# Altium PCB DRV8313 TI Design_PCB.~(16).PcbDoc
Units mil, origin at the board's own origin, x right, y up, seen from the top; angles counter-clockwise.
Board outline 2500 x 1250 mil, 2 copper layers (Top Layer, Bottom Layer), stack 62 mil thick; 47 components, 31 nets, 131 pads, 25 vias.
Unrouted connection lines stored in the file: 14.
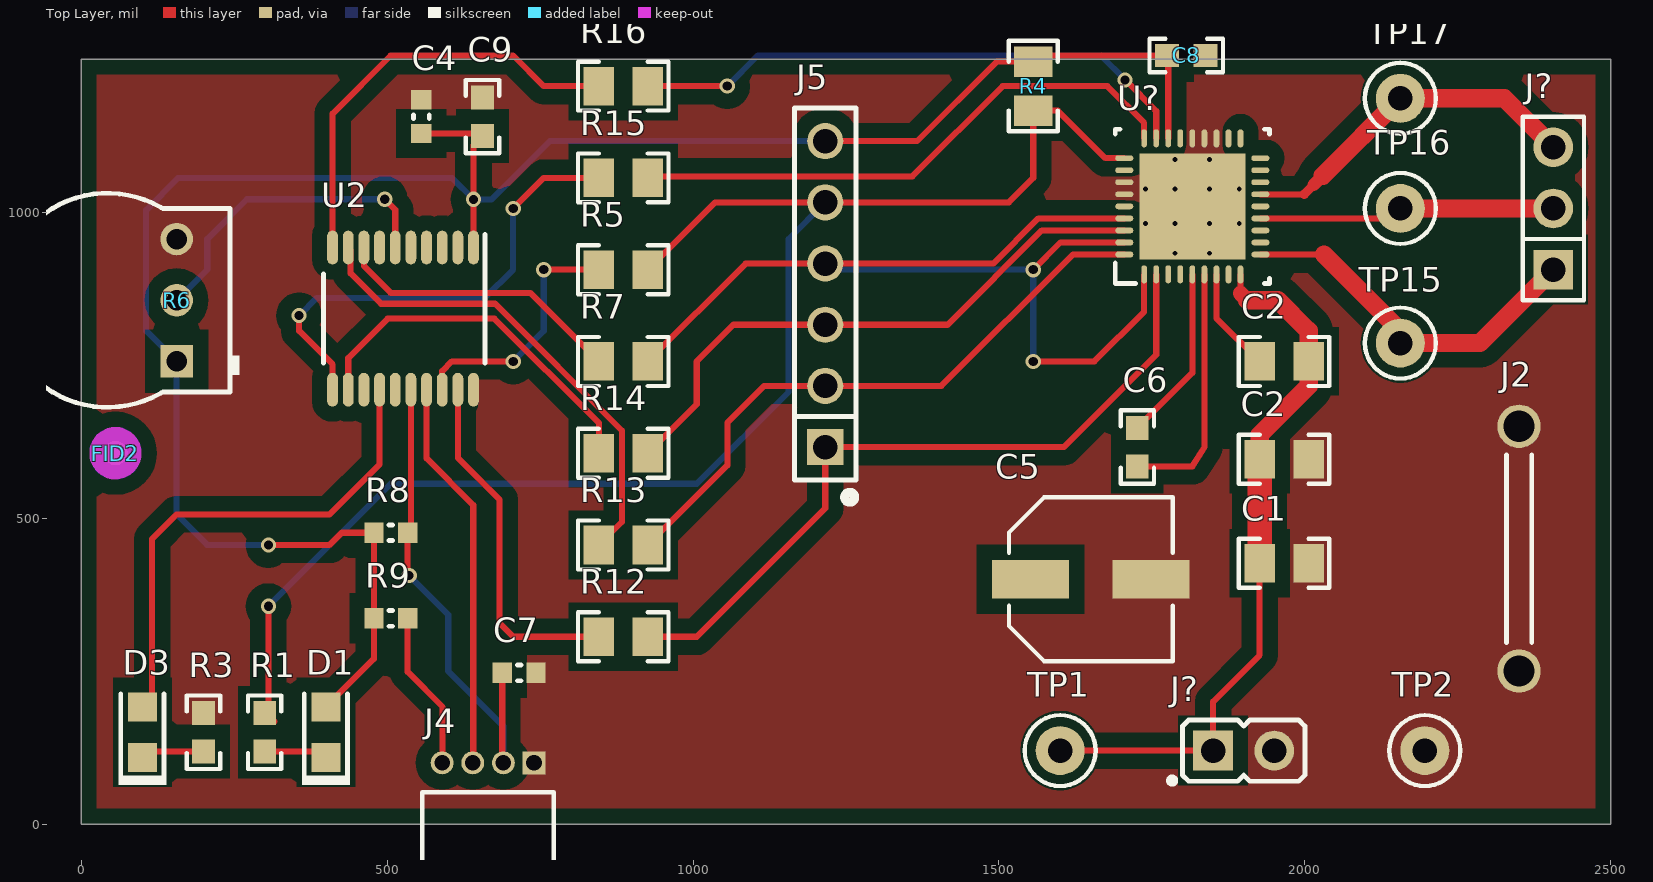
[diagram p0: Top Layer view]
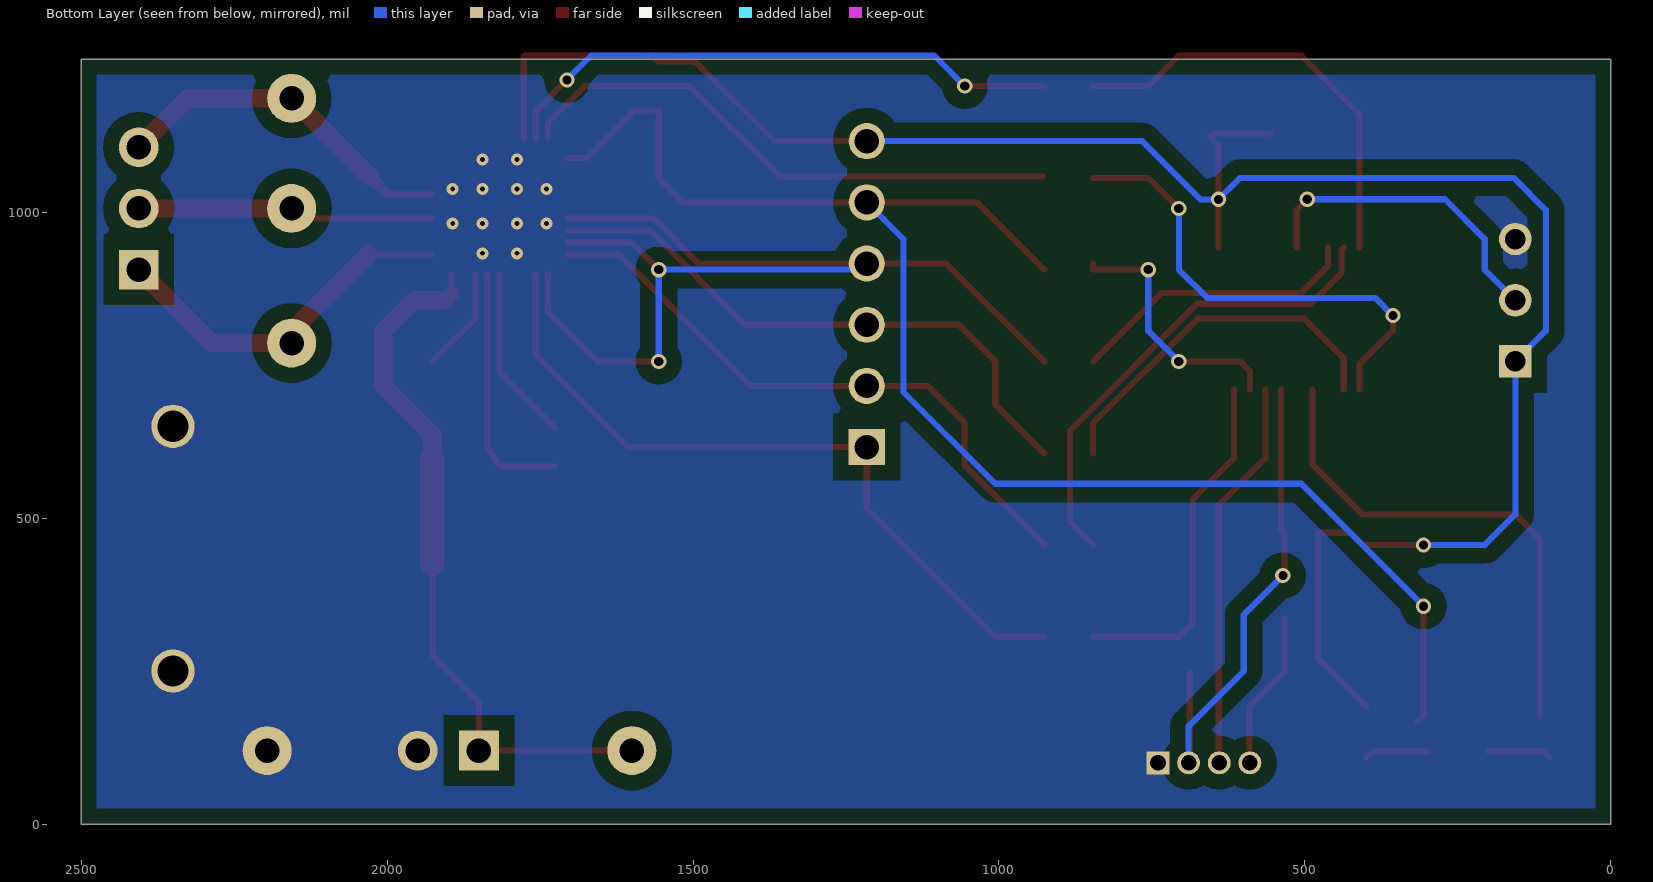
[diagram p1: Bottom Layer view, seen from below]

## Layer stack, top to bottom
Top Solder: solder mask 0.4, Solder Resist, Dk 3.5
Top Layer: signal copper 1.4
Dielectric1: core 59.2, FR-4, Dk 4.8
Bottom Layer: signal copper 1.4
Bottom Solder: solder mask 0.4, Solder Resist, Dk 3.5

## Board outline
0,0 0,1250 2500,1250 2500,0

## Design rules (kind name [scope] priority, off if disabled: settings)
AcuteAngle [All] p1: minimum=4.50000000000000E+0001 checktracksonly=FALSE
AssemblyTestPointUsage [All] p1: valid=2
BoardOutlineClearance BoardOutlineClearance_MountingHoles [OnCopper and InComponentClass('Mounting Holes')] p1: gap=40
BoardOutlineClearance BoardOutlineClearance_Poly [OnCopper and IsPoly] p2: gap=25
BoardOutlineClearance [OnCopper and Not InComponentClass('Logo') and not InComponentClass('FiducialMark') and not InRegion(1000,500,4000,800) and not InPoly] p3: gap=75
Clearance Clearance_Keepouts [((IsTrack Or IsArc) And Not InPoly) And IsFree and IsKeepOut vs ((IsTrack Or IsArc) And Not InPoly) And IsFree and IsKeepOut] p1: gap=0
Clearance Clearance_Poly [InPolygon] p2: gap=25
Clearance [All] p3: gap=7.87
ComponentClearance ComponentClearance_MountingHoles_FiducialMarks [InComponentClass('Mounting Holes') vs InComponentClass('FiducialMark')] p1: gap=50 collisioncheckmode=3 verticalgap=10 showdistances=FALSE
ComponentClearance ComponentClearance_Shunt [InComponentClass('Header') vs InComponentClass('Shunt')] p2: gap=0 collisioncheckmode=3 verticalgap=0 showdistances=FALSE
ComponentClearance ComponentClearance_Logo [InComponentClass('Logo')] p3: gap=50 collisioncheckmode=3 verticalgap=10 showdistances=FALSE
ComponentClearance ComponentClearance_ScrewToNut [(HasFootprint('NY PMS 440 0025 PH')) vs (HasFootprint('Keystone_1902C'))] p4: gap=5 collisioncheckmode=3 verticalgap=10 showdistances=FALSE
ComponentClearance ComponentClearance_MountingHoles [InComponentClass('Mounting Holes')] p5: gap=250 collisioncheckmode=3 verticalgap=100000 showdistances=FALSE
ComponentClearance ComponentClearance_SmallPassives [HasFootprint('0201*') or HasFootprint('0402*') or HasFootprint('0508') or HasFootprint('0603*') or HasFootprint('0612') or HasFootprint('0805*') or HasFootprint('0815*') or HasFootprint('0830*') or HasFootprint('1206*') or HasFootprint('1210*') or HasFootprint('1808*') or HasFootprint('1812*') or HasFootprint('1825*') or HasFootprint('2010*') or HasFootprint('2220*') or HasFootprint('2225*') or HasFootprint('2512*') or HasFootprint('2728*') or HasFootprint('3518*') vs HasFootprint('0201*') or HasFootprint('0402*') or HasFootprint('0508') or HasFootprint('0603*') or HasFootprint('0612') or HasFootprint('0805*') or HasFootprint('0815*') or HasFootprint('0830*') or HasFootprint('1206*') or HasFootprint('1210*') or HasFootprint('1808*') or HasFootprint('1812*') or HasFootprint('1825*') or HasFootprint('2010*') or HasFootprint('2220*') or HasFootprint('2225*') or HasFootprint('2512*') or HasFootprint('2728*') or HasFootprint('3518*')] p6: gap=14.96 collisioncheckmode=3 verticalgap=10 showdistances=FALSE
ComponentClearance ComponentClearance_THtoSMT [IsThruComponent vs IsSMTComponent] p7: gap=40 collisioncheckmode=3 verticalgap=30 showdistances=FALSE
ComponentClearance ComponentClearance_THtoTH [IsThruComponent vs IsThruComponent] p8: gap=30 collisioncheckmode=3 verticalgap=30 showdistances=FALSE
ComponentClearance [All] p9: gap=30 collisioncheckmode=3 verticalgap=10 showdistances=FALSE
DiffPairsRouting [All] p1: maxlimit=100 minlimit=10 mostfreqgap=10 toplayer_minwidth=15 toplayer_maxwidth=15 toplayer_prefwidth=15 bottomlayer_minwidth=15 bottomlayer_maxwidth=15 bottomlayer_prefwidth=15 maxuncoupledlength=1000
FabricationTestPointUsage TestPointUsage [All] p1: valid=2 allowmultiple=FALSE
FabricationTestpoint Testpoint [All] p1: side=3 testpointundercomponent=TRUE minsize=40 maxsize=100 preferedsize=60 minholesize=0 maxholesize=40 preferedholesize=32 testpointgrid=1 allowsidetop=TRUE allowsidebottom=TRUE usegrid=TRUE gridtolerance=0.01
FanoutControl Fanout_LCC [IsLCC] p1: bgadir=Out bgaviamode=Centered fanoutstyle=Auto fanoutdirection=Alternating viagrid=1 // Fanout_LCC (Default Rule)
FanoutControl Fanout_BGA [IsBGA] p2: bgadir=Out bgaviamode=Centered fanoutstyle=Auto fanoutdirection=Alternating viagrid=1 // Fanout_BGA (Default Rule)
FanoutControl Fanout_Default [All] p4: bgadir=Out bgaviamode=Centered fanoutstyle=Auto fanoutdirection=Alternating viagrid=1 // Fanout_Default (Default Rule)
FanoutControl Fanout_Small [(CompPinCount < 5)] p5: bgadir=Out bgaviamode=Centered fanoutstyle=Auto fanoutdirection=OutThenIn viagrid=1 // Fanout_Small (Default Rule)
HoleSize [All] p1: absolutevalues=TRUE maxlimit=251 minlimit=7.87 maxpercent=80.000 minpercent=20.000
MinimumAnnularRing MinimumAnnularRing_ThermalPadVias [IsVia and InAnyComponent] p1: minimumring=5.91
MinimumAnnularRing [All] p2: minimumring=8
MinimumSolderMaskSliver MinimumSolderMaskSliver_Logo [InComponentClass('Logo') vs InComponentClass('Logo')] p1: minsoldermaskwidth=0.7
MinimumSolderMaskSliver [All] p2: minsoldermaskwidth=3.94
PlaneConnect [All] p1: planeconnectstyle=Relief reliefexpansion=10 reliefentries=4 reliefconductorwidth=10 reliefairgap=10
PolygonConnect [All] p1: connectstyle=Direct reliefconductorwidth=10 reliefentries=4 polygonreliefangle="90 Angle" airgapwidth=10
RoutingVias ThermalPadVias [IsVia and InAnyComponent] p1: holewidth=7.87 width=19.68 viastyle="Through Hole" minholewidth=7.87 minwidth=19.68 maxholewidth=12.99 maxwidth=23.62
RoutingVias [All] p2: holewidth=16 width=34 viastyle="Through Hole" minholewidth=7.87 minwidth=26 maxholewidth=40 maxwidth=65
SilkToBoardRegionClearance [Not ((IsComment or IsDesignator) And (Hide <> 'False')) and not InRegion(1000,500,4000,800)] p1:
SilkToSilkClearance SilkToSilkClearance_Pb-FreeLogo [(HasFootprint('Pb-Free_Overlay_Medium') OR HasFootprint('Pb-Free_Overlay_Small')) vs (HasFootprint('Pb-Free_Overlay_Medium') OR HasFootprint('Pb-Free_Overlay_Small'))] p1: silktosilkclearance=0
SilkToSilkClearance [All] p2: silktosilkclearance=4
SilkToSolderMaskClearance SilkToComponentPadClearance [IsPad and InAnycomponent] p1: minsilkscreentomaskgap=5 clearancetoexposedcopper=TRUE
SilkToSolderMaskClearance "Silk to Solder Mask Opening" [All] p2: minsilkscreentomaskgap=4 clearancetoexposedcopper=FALSE
SolderMaskExpansion [All] p1: expansion=1.97
Width [All] p1: maxlimit=100 minlimit=6 preferedwidth=10 checkconnectedcopper=TRUE
15 further rules are at their usual default settings.

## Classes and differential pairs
component class Logo: Logo1
component class FiducialMark: FID1 FID2 FID3
component class AssemblyNote: ZZ1 ZZ2 ZZ3 ZZ4
component class Label: LBL1
component class Header: J5 J?

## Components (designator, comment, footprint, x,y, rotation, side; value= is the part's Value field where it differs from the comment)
C1 "C2012X5R2A104K125AA" 0805_HV 1966.02,426.02 r180 top
C2 "C2012X5R2A104K125AA" 0805_HV 1966.02,756.02 r0 top
C2 "C2012X5R2A104K125AA" 0805_HV 1966.02,596.02 r0 top
C4 "C0603C104K8RACTU" 0603L 556.02,1156.02 r90 top
C5 "EEE-FK1K100XP" SM_RADIAL_D8 1650,400 r0 top
C6 "0.01uF" 0603 1726.02,616.02 r270 top
C7 "GRM188R71C102KA01D" 0603L 715.82,247.02 r0 top
C8 "GCM188R71C474KA55D" 0603 1806.02,1256.02 r0 top
C9 "GCM188R71C474KA55D" 0603 656.02,1156.02 r90 top
D1 "LTST-C170KRKT" LED_LTST-C170_Red 400,150 r270 top
D3 "LTST-C170KGKT" LTST-C170KGKT_Green 100,150 r270 top
FID1 "Fiducial" Fiducial10-20 640,3150 r0 top
FID2 "Fiducial" Fiducial10-20 56.02,606.02 r0 top
FID3 "Fiducial" Fiducial10-20 4320,300 r0 top
J2 "D3082-05" Harwin_D3082-05 2350,450 r90 top
J4 "851-43-004-20-001000" CONN_851-43-004-20-001000 665,100 r0 top
J5 "PEC06SAAN" Sullins_PEC06SAAN 1216.02,866.02 r90 top
J? "PBC02SAAN" Sullins_PBC02SAAN 1900,120 r90 top
J? "PBC03SAAN" PBC03SAAN 2406.02,1006.02 r90 top
LBL1 "Size: 0.65\" x 0.20 \"" Label_650x200 4650,1140.66 r0 top
Logo1 "Texas Instruments" TI_Stacked_Overlay_Small 4450,800 r0 top
Logo2 "Pb-Free Symbol" Pb-Free_Overlay_Small 4620,640 r0 top
Logo3 "FCC disclaimer" FCC_disclaimer 2350,3380 r0 top
R1 "CRCW0603330RJNEA" 0603 300,150 r90 top
R3 "CRCW0603330RJNEA" 0603 200,150 r90 top
R4 "CRCW080510K0JNEA" 0805_HV 1556.02,1206.02 r90 top
R5 "ERJ-6GEY0R00V" 0805_HV 886.02,906.02 r0 top
R6 "3352T-1-503LF" Bourns_3352T 156.02,856.02 r90 top
R7 "ERJ-6GEY0R00V" 0805_HV 886.02,756.02 r0 top
R8 "CRCW060347K0JNEA" 0603L 506.02,476.02 r180 top
R9 "CRCW06030000Z0EA" 0603L 506.02,336.02 r180 top
R12 "ERJ-6GEY0R00V" 0805_HV 886.02,306.02 r0 top
R13 "ERJ-6GEY0R00V" 0805_HV 886.02,456.02 r0 top
R14 "ERJ-6GEY0R00V" 0805_HV 886.02,606.02 r0 top
R15 "ERJ-6GEY0R00V" 0805_HV 886.02,1056.02 r0 top
R16 "ERJ-6GEY0R00V" 0805_HV 886.02,1206.02 r0 top
TP1 "5000" Keystone5000 1600,120 r0 top
TP2 "5001" Keystone5001 2196.02,120 r0 top
TP15 "5002" Keystone5002 2156.02,786.02 r0 top
TP16 "5002" Keystone5002 2156.02,1006.02 r0 top
TP17 "5002" Keystone5002 2156.02,1186.02 r0 top
U2 "MSP430G2553IPW20R" PW0020A_N 526.02,826.02 r270 top
U? "DRV8313RHHR" RHH0036C 1816.02,1009.45 r90 top
ZZ1 "This Assembly Note is for PCB labels only" AssemblyNoteLabel 355,7548 r0 top
ZZ2 "These assemblies are ESD sensitive, ESD precautions shall be observed." AssemblyNote 355,7439.11 r0 top
ZZ3 "These assemblies must be clean and free from flux and all contaminants. Use of no clean flux is not acceptable." AssemblyNote 355,7350.56 r0 top
ZZ4 "These assemblies must comply with workmanship standards IPC-A-610 Class 2, unless otherwise specified." AssemblyNote 355,7262 r0 top

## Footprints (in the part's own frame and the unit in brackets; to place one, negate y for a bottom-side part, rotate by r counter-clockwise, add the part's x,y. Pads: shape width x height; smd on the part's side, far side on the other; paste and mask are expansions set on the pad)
0603 [mm] "0603 from SM-752 data"
  rect 1x0.95 smd: 1(-0.8,0) 2(0.8,0)
  silkscreen extent -1.52,-0.69 1.52,0.69, body extent -0.87,-0.47 0.87,0.47, height 1
0603L [mm] "0603 from SM-752 data"
  rect 0.8x0.85 smd: 1(-0.7,0) 2(0.7,0)
  silkscreen extent -0.07,-0.33 0.07,0.33, body extent -0.87,-0.47 0.87,0.47, height 1
0805_HV [mil] "0805 with 30mil clearance between pads"
  rect 50x63 smd: 1(-40,0) 2(40,0)
  silkscreen extent -74,-40 74,40, body extent -43,-29 43,29, height 57
AssemblyNote [mil] "Assembly Note"
AssemblyNoteLabel [mil] "Assembly Note for PCB Labels"
Bourns_3352T [mm] "TH, 3-Leads, Body 9.53x8.89mm, Pitch 2.54mm"
  rect 1.35x1.35 hole 0.85: 1(-2.54,0)
  round 1.35 hole 0.85: 2(0,0) 3(2.54,0)
  silkscreen extent -4.44,-2.6 4.44,7.31, body extent -4.44,-2.21 4.45,7.32, height 3.81
CONN_851-43-004-20-001000 [mm] "MILL-MAX"
  rect 0.95x0.95 hole 0.65: 1(1.905,0)
  round 0.95 hole 0.65: 2(0.635,0) 3(-0.635,0) 4(-1.905,0)
  silkscreen extent -2.73,-5.31 2.73,-1.22, body extent -2.73,-5.31 2.73,0.23, height 2.23
FCC_disclaimer [mil]
Fiducial10-20 [mm]
  round 1 smd mask+0.5: 1(0,0)
  Top Layer keep-out circle w1.178: c0,0 r0.5
Harwin_D3082-05 [mm] "Shorting Plug, 10.16mm spacing, TH"
  round 1.8 hole 1.3: 1(-5.08,0) 2(5.08,0)
  silkscreen extent -3.9,-0.53 3.9,0.53, body extent -5.6,-0.52 5.61,0.52, height 6.63
Keystone5000 [mil] "For Keystone 500x miniature loop terminals"
  round 80 hole 40: 1(0,0)
  silkscreen extent -58,-58 58,58, body extent -49,-49 49,49, height 182
Keystone5001 [mil] "For Keystone 500x miniature loop terminals"
  round 80 hole 40: 1(0,0)
  silkscreen extent -58,-58 58,58, body extent -49,-49 49,49, height 182
Keystone5002 [mil] "For Keystone 500x miniature loop terminals"
  round 80 hole 40: 1(0,0)
  silkscreen extent -58,-58 58,58, body extent -49,-49 49,49, height 182
Label_650x200 [mil] "Thermal Transfer Label"
  silkscreen extent -325,-100 325,100, body extent -325,-100 325,100, height 1
LED_LTST-C170_Red [mm] "LITE-ON"
  rect 1.2x1.2 smd: 1(-1.05,0) 2(1.05,0)
  silkscreen extent -1.6,-1 2.2,1, body extent -1.05,-0.67 1.05,0.67, height 1.1
LTST-C170KGKT_Green [mm] "LITE-ON"
  rect 1.2x1.2 smd: 1(-1.05,0) 2(1.05,0)
  silkscreen extent -1.6,-1 2.2,1, body extent -1.05,-0.67 1.05,0.67, height 1.1
Pb-Free_Overlay_Small [mil]
  silkscreen extent -46,-46 46,46
PBC03SAAN [mm] "Sullins 100mil, 1x3, 230 mil above insulator"
  rect 1.65x1.65 hole 1.016: 1(-2.54,0)
  round 1.65 hole 1.016: 2(0,0) 3(2.54,0)
  silkscreen extent -3.81,-1.27 3.81,1.27, body extent -3.81,-1.27 3.81,1.27, height 8.38
PW0020A_N [mm] "TSOP, 20-Leads, Body 6.5x4.4mm, Pitch 0.65mm, IPC Medium Density"
  oval 1.4x0.45 smd: 1(-2.95,2.925) 2(-2.95,2.275) 3(-2.95,1.625) 4(-2.95,0.975) 5(-2.95,0.325) 6(-2.95,-0.325) 7(-2.95,-0.975) 8(-2.95,-1.625) 9(-2.95,-2.275) 10(-2.95,-2.925) 11(2.95,-2.925) 12(2.95,-2.275) 13(2.95,-1.625) 14(2.95,-0.975) 15(2.95,-0.325) 16(2.95,0.325) 17(2.95,0.975) 18(2.95,1.625) 19(2.95,2.275) 20(2.95,2.925)
  silkscreen extent -3.5,-3.3 1.85,3.4, body extent -3.21,-3.25 3.21,3.25, height 1
RHH0036C [mm] "QFN, 36-Leads, Body 6x6mm, Pitch 0.5mm, Thermal Pad 4.4x4.4mm, TI Recommended"
  oval 0.75x0.24 smd: 1(-2.825,2) 2(-2.825,1.5) 3(-2.825,1) 4(-2.825,0.5) 5(-2.825,0) 6(-2.825,-0.5) 7(-2.825,-1) 8(-2.825,-1.5) 9(-2.825,-2) 19(2.825,-2) 20(2.825,-1.5) 21(2.825,-1) 22(2.825,-0.5) 23(2.825,0) 24(2.825,0.5) 25(2.825,1) 26(2.825,1.5) 27(2.825,2)
  oval 0.24x0.75 smd: 10(-2,-2.825) 11(-1.5,-2.825) 12(-1,-2.825) 13(-0.5,-2.825) 14(0,-2.825) 15(0.5,-2.825) 16(1,-2.825) 17(1.5,-2.825) 18(2,-2.825) 28(2,2.825) 29(1.5,2.825) 30(1,2.825) 31(0.5,2.825) 32(0,2.825) 33(-0.5,2.825) 34(-1,2.825) 35(-1.5,2.825) 36(-2,2.825)
  rect 4.4x4.4 smd paste-2.2: 37(0,0)
  silkscreen extent -3.2,-3.2 3.2,3.2, body extent -3.05,-3.05 3.05,3.05, height 1.01
SM_RADIAL_D8 [mm] "6.3 x 7.7mm:  Panasonic D8"
  rect 3.2x1.6 smd: 1(-2.5,0) 2(2.5,0)
  silkscreen extent -3.4,-3.4 3.4,3.4, body extent -3.4,-3.4 3.4,3.4, height 8.01
Sullins_PBC02SAAN [mm] "Sullins 100mil, 1x2, 230 mil above insulator"
  rect 1.65x1.65 hole 1.016: 1(0,1.27)
  round 1.65 hole 1.016: 2(0,-1.27)
  silkscreen extent -1.37,-2.54 1.27,3.1, body extent -1.27,-2.54 1.27,2.54, height 8.38
Sullins_PEC06SAAN [mm] "TH, 6-Leads, Body 608x100mil, Pitch 100mil"
  rect 1.5x1.5 hole 1.016: 1(-6.35,0)
  round 1.5 hole 1.016: 2(-3.81,0) 3(-1.27,0) 4(1.27,0) 5(3.81,0) 6(6.35,0)
  silkscreen extent -8.64,-1.27 7.72,1.27, body extent -7.72,-1.27 7.72,1.27, height 8.59
TI_Stacked_Overlay_Small [mil]
  silkscreen extent -418,-98 418,98

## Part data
C1 C2 C2: "CAP, CERM, 0.1 µF, 100 V, +/- 10%, X5R, 0805"
C4: "CAP, CERM, 0.1 µF, 10 V, +/- 10%, X7R, 0603"
C5: "CAP, AL, 10 µF, 80 V, +/- 20%, 2.4 ohm, AEC-Q200 Grade 2, SMD"
C6: library part Cap, "Capacitor"
C7: "CAP, CERM, 1000 pF, 16 V, +/- 10%, X7R, 0603"
C8 C9: "CAP, CERM, 0.47 µF, 16 V, +/- 10%, X7R, AEC-Q200 Grade 1, 0603"
D1: "LED, Red, SMD"
D3: "LED, Green, SMD"
FID1 FID2 FID3: "Fiducial mark.  There is nothing to buy or mount."
J2: "1mm Uninsulated Shorting Plug, 10.16mm spacing, TH"
J4: "SOCKET .050\" GRID SIP 4 POS R/A, TH"
J5: "Header, 100mil, 6x1, Tin, TH"
J?: "Header, 100mil, 2x1, Gold, TH"
J?: "Header, 100mil, 3x1, Gold, TH"
LBL1: library part THT-14-423-10, "Thermal Transfer Printable Labels, 0.650\" W x 0.200\" H - 10,000 per roll"
Logo1: library part TI_Logo, "Texas Instrument Corporate Signature"
Logo2: library part Pb-Free
Logo3: library part FCC_disclaimer, "FCC_disclaimer"
R1 R3: "RES, 330, 5%, 0.1 W, 0603"
R4: "RES, 10 k, 5%, 0.125 W, 0805"
R5 R7 R12 R13 R14 R15 R16: "RES, 0, 5%, 0.125 W, 0805"
R6: "Trimming Potentiometer, 50K, 0.5W, TH"
R8: "RES, 47 k, 5%, 0.1 W, 0603"
R9: "RES, 0, 5%, 0.1 W, 0603"
TP1: "Test Point, Miniature, Red, TH"
TP2: "Test Point, Miniature, Black, TH"
TP15 TP16 TP17: "Test Point, Miniature, White, TH"
U2: "16 MHz Mixed Signal Microcontroller with 16 KB Flash, 512 B SRAM and 24 GPIOs, -40 to 85 degC, 20-pin SOP (PW), Green (RoHS & no Sb/Br)"
U?: "2.5-A Triple 1/2-H Bridge Driver, RHH0036C"
ZZ1: library part AssemblyNoteLabel
ZZ2 ZZ3 ZZ4: library part AssemblyNote

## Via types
v1: diameter 25, hole 15, Top Layer to Bottom Layer, 13 vias
v2: diameter 19.68, hole 7.87, Top Layer to Bottom Layer, 12 vias

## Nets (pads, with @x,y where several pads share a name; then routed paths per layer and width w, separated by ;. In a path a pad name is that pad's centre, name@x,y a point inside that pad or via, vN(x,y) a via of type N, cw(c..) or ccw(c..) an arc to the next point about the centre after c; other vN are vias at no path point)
CPH: C6.2 U?.6 | length 409.5
  Top Layer w10: C6.2 1816.02,584.53 1836.02,616.02 U?.6
CPL: C6.1 U?.5 | length 288
  Top Layer w10: C6.1 1816.02,737.52 U?.5
EN: J5.4 R7.2 U?.1 U?.33 U?.35 | length 1812.8
  Top Layer w10: R7.2 1086.02,916.02 J5.4 1490.75,916.02 1564.49,989.77 U?.33 ; v1(1556.02,756.02) 1656.02,756.02 1737.28,837.28 U?.1 ; v1(1556.02,906.02) 1600.4,950.4 U?.35
  Bottom Layer w10: J5.4 1226.02,906.02 v1(1556.02,906.02) v1(1556.02,756.02)
GND: C1.1 C2.2@2006.02,596.02 C4.2 C5.2 C7.2 C8.2 C9.2 J2.1 J2.2 J4.1 J?.2@1950,120 R3.2 R6.3 TP2.1 U2.20 U?.3 U?.11 U?.12 U?.16 U?.17 U?.20 U?.21 U?.22 U?.23 U?.24 U?.29 U?.30 U?.31 U?.32 U?.37
  other v2: 1787.87,932.68 1844.17,932.68 1739.25,981.31 1787.87,981.31 1844.17,981.31 1892.8,981.31 1739.25,1037.6 1787.87,1037.6 1844.17,1037.6 1892.8,1037.6 1787.87,1086.23 1844.17,1086.23
IN1: J5.1 R12.2 U?.2 | length 1211.7
  Top Layer w10: R12.2 1006.02,306.02 1216.02,516.02 J5.1 1606.02,616.02 1756.97,766.97 U?.2
IN2: J5.2 R13.2 U?.36 | length 1016.4
  Top Layer w10: R13.2 1056.02,586.02 1056.02,656.02 1116.02,716.02 J5.2 1406.02,716.02 1620.71,930.71 U?.36
IN3: J5.3 R14.2 U?.34 | length 970.6
  Top Layer w10: R14.2 1006.02,686.02 1006.02,756.02 1066.02,816.02 J5.3 1416.02,816.02 1570.08,970.08 U?.34
NetD1_2: D1.2 R1.1 | length 104.1
  Top Layer w10: R1.1 390.16,118.5 D1.2
NetD3_2: D3.2 R3.1 | length 104.1
  Top Layer w10: D3.2 109.84,118.5 R3.1
NetJ4_4: J4.4 R9.1 | length 258.9
  Top Layer w10: R9.1 533.58,248.46 590.82,191.23 J4.4@590.82,100.82
NetR5_1: R5.1 U2.18 | length 423.5
  Top Layer w10: U2.18 590,740 606.02,756.02 v1(706.02,756.02) ; v1(756.02,906.02) R5.1 R5.1@846.02,916.02
  Bottom Layer w10: v1(706.02,756.02) 756.02,806.02 v1(756.02,906.02)
NetR7_1: R7.1 U2.8 | length 478.7
  Top Layer w10: U2.8 462.05,912.05 506.02,868.07 733.98,868.07 R7.1
NetR15_1: R15.1 U2.11 | length 785.6
  Top Layer w10: v1(356.02,831.02) 356.02,806.02 410.87,751.18 U2.11 ; v1(706.02,1006.02) 756.02,1056.02 R15.1
  Bottom Layer w10: v1(356.02,831.02) 384.88,859.88 659.88,859.88 706.02,906.02 v1(706.02,1006.02)
NetR16_1: R16.1 U2.10 | length 714
  Top Layer w10: U2.10 410.87,1160.87 506.02,1256.02 706.02,1256.02 756.02,1206.02 R16.1
NFAULT: J5.5 R1.2 R4.1 R5.2 U?.28 | length 2505.6
  Top Layer w10: v1(306.02,356.02) 306.02,177.52 R1.2@316.02,167.52 ; R5.2 1036.02,1016.02 J5.5 1516.02,1016.02 1556.02,1056.02 R4.1 1596.02,1166.02 1673.85,1088.19 U?.28
  Bottom Layer w10: v1(306.02,356.02) 506.02,556.02 1006.02,556.02 1156.02,706.02 1156.02,956.02 J5.5
NRESET: R16.2 U?.26 | length 933.7
  Top Layer w10: R16.2 v1(1056.02,1206.02) ; v1(1706.02,1216.02) 1756.97,1165.08 U?.26
  Bottom Layer w10: v1(1056.02,1206.02) 1106.02,1256.02 1666.02,1256.02 v1(1706.02,1216.02)
NSLEEP: R15.2 U?.27 | length 920.1
  Top Layer w10: R15.2@928.43,1058.43 1358.43,1058.43 1506.02,1206.02 1677.12,1206.02 1737.28,1145.86 U?.27
OUT1: TP15.1 U?.10 | length 600.1
  Top Layer w10: U?.10 2031.33,930.71
  Top Layer w30: 2031.33,930.71 2156.02,806.02 TP15.1 2286.02,786.02 2406.02,906.02
OUT2: TP16.1 U?.13 | length 485.5
  Top Layer w10: U?.13 TP16.1@2139.77,989.77
  Top Layer w30: TP16.1@2139.77,989.77 TP16.1 2406.02,1006.02
OUT3: TP17.1 U?.15 | length 576.8
  Top Layer w10: U?.15 1998.85,1029.14
  Top Layer w15: 1998.85,1029.14 2013.91,1044.2
  Top Layer w20: 2013.91,1044.2 2028.96,1059.26
  Top Layer w30: 2028.96,1059.26 TP17.1@2155.85,1186.14 ; TP17.1 2326.02,1186.02 2406.02,1106.02
POT: R6.2 U2.6 | length 523.6
  Top Layer w10: v1(496.02,1021.02) 513.23,1003.82 U2.6
  Bottom Layer w10: R6.2 206.02,906.02 206.02,956.02 271.02,1021.02 v1(496.02,1021.02)
PUSH: U2.7
PWMA: R12.1 U2.19 | length 581.3
  Top Layer w10: U2.19 615.59,598.31 683.97,529.93 683.97,328.08 706.02,306.02 R12.1
PWMB: R13.1 U2.9 | length 796.4
  Top Layer w10: U2.9 440.31,938.31 440.31,900.01 490.13,850.2 676.56,850.2 883.9,642.86 883.9,493.9 R13.1
PWMC: R14.1 U2.12 | length 608
  Top Layer w10: U2.12 436.46,761.46 501.02,826.02 675.46,826.02 846.02,655.45 R14.1
RESET: C7.1 J4.2 R8.1 U2.16 | length 811.3
  Top Layer w10: v1@533.58,408.46 R8.1 ; R8.1@538.82,481.26 U2.16 ; J4.2@688.26,101.74 C7.1
  Bottom Layer w10: v1(536.02,406.02) 600,342.05 600,250 690,160 J4.2
STATUS: D3.1 U2.14 | length 832.9
  Top Layer w10: D3.1@116.02,177.36 116.02,466.02 156.02,506.02 406.02,506.02 487.64,587.64 U2.14
TEST: J4.3 U2.17 | length 640.7
  Top Layer w10: U2.17 564.41,597.64 640.82,521.23 J4.3@640.82,100.82
V3P3: C4.1 C8.1 C9.1 D1.1 J5.6 R4.2 R6.1 R8.2 R9.2 U2.1 U?.25 | length 3411.7
  Top Layer w10: v1(306.02,456.02) 406.02,456.02 426.02,476.02 R8.2 R9.2 478.46,269.8 D1.1 ; C4.1 C9.1@652.09,1128.46 ; U2.1 v1(641.18,1020.87) 641.18,1109.68 C9.1 ; J5.6@1211.14,1116.02 J5.6 1366.02,1116.02 1496.02,1246.02 R4.2 1566.02,1256.02 C8.1 ; U?.25 C8.1@1776.65,1253.9
  Bottom Layer w10: v1(306.02,456.02) 206.02,456.02 156.02,506.02 R6.1 106.02,806.02 106.02,1003.48 158.57,1056.02 606.02,1056.02 v1(641.18,1020.87) 670.87,1020.87 766.02,1116.02 J5.6
VCP: C2.1@1926.02,756.02 U?.7 | length 171.5
  Top Layer w10: U?.7 1855.39,826.65 C2.1@1926.02,756.02
VM: C1.2 C2.1@1926.02,596.02 C2.2@2006.02,756.02 C5.1 J?.1@1850,120 TP1.1 U?.9 U?.19 | length 1178.2
  Top Layer w10: TP1.1 1850,120 1850,200 1926.02,276.02 C1.2 ; 1894.76,867.28 U?.9
  Top Layer w25: 1894.76,867.28 1906.02,856.02
  Top Layer w30: 1906.02,856.02 1956.02,856.02 2006.02,806.02 C2.2@2006.02,756.02 ; C2.1@1926.02,596.02 1926.02,636.02 2006.02,716.02 C2.2@2006.02,766.02
  Top Layer w40: C1.2 C2.1@1926.02,596.02
pads on no net: FID1.1 FID2.1 FID3.1 J?.1@2406.02,906.02 J?.2@2406.02,1006.02 J?.3 U2.2 U2.3 U2.4 U2.5 U2.13 U2.15 U?.4 U?.8 U?.14 U?.18

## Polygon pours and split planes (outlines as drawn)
GND on Top Layer "TOP_LAYER_GND_P002" (solid, remove dead copper, pour order 2): 0,0 2500,0 2500,1250 0,1250 0,0
GND on Bottom Layer "BOTTOM_LAYER_GND_P008" (solid, remove dead copper, pour order 8): 0,0 2500,0 2500,1250 0,1250 0,0

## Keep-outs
Keep-Out Layer:
  text ".Layer_Name" at 577,-858.49 h60

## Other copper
Top Layer:
  text ".Layer_Name" at 577,-858.49 h60
Bottom Layer:
  text ".Layer_Name" at 577,-858.49 h60

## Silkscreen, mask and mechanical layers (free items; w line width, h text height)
Top Overlay:
  region: 4700,520 4400,520 4400,420 4700,420
  text "This document can handle board shapes up to 7.9in x 10in, although" at 0,6345 h60
  text "our panel vendors top out at 7in x 10in." at 0,6220.94 h60
  text "To re-size the board shape, do the following:" at 55,6096.88 h60
  text "Select lines on M1 Board Outline and delete (easy in single layer mode...shift+s)" at 115,5972.82 h60
  text "Draw a rectangle using lines (example will be for a 4\" x 6\" board" at 115,5848.76 h60
  text "Enter Place Line mode (keyboard pl)" at 325,5724.71 h60
  text "keyboard jo to jump to origin, hit enter" at 325,5600.65 h60
  text "keyboard jl to jump to location, set x to 6000, hit enter twice" at 325,5476.59 h60
  text "keyboard jl to jump to location, set x to 6000 and y to 4000, hit enter twice" at 325,5352.53 h60
  text "keyboard jl to jump to location, set x to 0 and y to 4000, hit enter twice" at 325,5228.47 h60
  text "keyboard jo to jump to origin, hit enter" at 325,5104.41 h60
  text "Hit ESC twice to exit place line mode" at 325,4980.35 h60
  text "Select lines on M1 Board Outline" at 115,4836.3 h60
  text "Menu Design|Board Shape|Define from Selected Objects (keyboard dsd)" at 115,4732.24 h60
  text "If you re-size the board, don't forget to move the drill table strings on the" at 0,4413 h60
  text "Drill Drawing Layer...they should be just to the right of your board shape" at 193,4307 h60
  text "'.PRJ_Number'.PCB_Rev-" at 4370,120 h108.27
  text ".Layer_Name" at 577,-858.49 h60
Bottom Overlay:
  text ".Layer_Name" at 577,-858.49 h60
Top Paste:
  text ".Layer_Name" at 577,-858.49 h60
Bottom Paste:
  text ".Layer_Name" at 577,-858.49 h60
Top Solder:
  text ".Layer_Name" at 577,-858.49 h60
  text ".Layer_Name" at 577,-858.49 h60
Bottom Solder:
  text ".Layer_Name" at 577,-858.49 h60
Drill Guide:
  text ".Layer_Name" at 577,-858.49 h60
M1 Board Outline:
  lines w10: 0,0 2500,0 ; 0,0 0,1250 ; 0,0 2500,0 ; 0,0 0,1250 ; 0,1250 2500,1250 ; 0,1250 2500,1250 ; 2500,0 2500,1250 ; 2500,0 2500,1250
  text ".Layer_Name" at 577,-858.49 h60
M2 Board Dimensions:
  rectangle: 0,-275 125,-150
  rectangle: 125,-400 500,-275
  lines w7: 0,-275 1000,-275 ; 125,-400 125,-150 ; 250,-400 250,-150 ; 500,-400 500,-150 ; 750,-400 750,-150 ; 0,-400 1000,-400 1000,-150 0,-150 0,-400
  text ".Layer_Name" at 577,-858.49 h60
M3 3D STEP Top:
  text ".Layer_Name" at 577,-858.49 h60
M4 3D STEP Bottom:
  text ".Layer_Name" at 577,-858.49 h60
M5 Assembly Top:
  lines w10: -292,-930.17 6308,-930.17 ; -292,-726.83 6310,-726.83 ; -292,-523.5 -292,-1133.5 3713,-1133.5 6310,-1133.5 6310,-523.5 -291.5,-523.5 -291.5,-1133.5 1284,-1133.5 ; 2173,-1133.5 2173,-523.5 ; 3440,-726.83 3440,-523.5 ; 4280,-726.83 4280,-523.5 ; 4902,-1140 4902,-937.17
  text "COMPONENTS MARKED 'DNP' SHOULD NOT BE POPULATED." at 1153.5,-318.5 h60
  text "ASSEMBLY VARIANT:" at 1153,-434 h60
  text ".VariantName" at 2189,-434 h60
  text "PCB VIEWED FROM TOP SIDE" at -228.5,-655.67 h60
  text "BOARD #:" at 2248,-655.67 h60
  text ".PRJ_Number" at 2793.5,-655.67 h60
  text "REV:" at 3638,-655.67 h60
  text ".PCB_Rev" at 3929.5,-655.67 h60
  text "SVN REV:" at 4476,-655.67 h60
  text ".VersionControl_RevNumber" at 4982,-655.67 h60
  text "TID #:" at 2248,-859 h60
  text ".TID" at 2793.5,-859 h60
  text "PLOT NAME =" at -228.5,-1064.34 h60
  text ".plot_File_Name" at 577,-1064.34 h60
  text "GENERATED    :" at 2250,-1064.34 h60
  text ".Print_Date" at 3119.5,-1064.34 h60
  text ".Print_Time" at 3848.5,-1064.34 h60
  text "TEXAS INSTRUMENTS" at 5113,-1064.34 h60
M6 Assembly Bottom:
  lines w10: -292.5,-727.33 6309.5,-727.33 ; -290.5,-930.67 6309.5,-930.67 ; 1115.5,-1140.5 1115.5,-937.67 ; 1737.5,-727.33 1737.5,-524 ; 2577.5,-727.33 2577.5,-524 ; 3844.5,-1134 3844.5,-524 ; 4733.5,-1134 6309,-1134 6309,-524 -292.5,-524 -292.5,-1134 2304.5,-1134 6309.5,-1134 6309.5,-524
  text "COMPONENTS MARKED 'DNP' SHOULD NOT BE POPULATED." at 6102,-318 h60
  text ".VariantName" at 5058,-434 h60
  text "ASSEMBLY VARIANT:" at 6097,-434 h60
  text ".VersionControl_RevNumber" at 1035.5,-656.17 h60
  text "SVN REV:" at 1541.5,-656.17 h60
  text ".PCB_Rev" at 2088,-656.17 h60
  text "REV:" at 2379.5,-656.17 h60
  text ".PRJ_Number" at 3224,-656.17 h60
  text "BOARD #:" at 3769.5,-656.17 h60
  text "PCB VIEWED FROM BOTTOM SIDE" at 6246,-656.17 h60
  text ".TID" at 3224,-859.5 h60
  text "TID #:" at 3769.5,-859.5 h60
  text "TEXAS INSTRUMENTS" at 904.5,-1064.84 h60
  text ".Print_Time" at 2169,-1064.84 h60
  text ".Print_Date" at 2898,-1064.84 h60
  text "GENERATED    :" at 3767.5,-1064.84 h60
  text ".plot_File_Name" at 5440.5,-1064.84 h60
  text "PLOT NAME =" at 6246,-1064.84 h60
M9 Title Sheet:
  drawing of 57 lines, arcs and shapes, not listed
  text "1" at 739.84,8036.5 h70
  text "2" at 3235.5,8036.5 h70
  text "3" at 5724.84,8036.5 h70
  text "4" at 8231.51,8036.5 h70
  text "5" at 10730.5,8036.5 h70
  text "6" at 13235.5,8036.5 h70
  text "A" at -416.5,6893.5 h70
  text "A" at 14383.5,6893.5 h70
  text "B" at -416.5,4513.5 h70
  text "B" at 14383.5,4513.5 h70
  text "C" at -416.5,2138.5 h70
  text "C" at 14383.5,2138.5 h70
  text "PROJECT TITLE:" at 11343.5,277.5 h45
  text ".PRJ_Title" at 11393.5,144.17 h70
  text "DESIGNED FOR:" at 11343.5,-23.5 h45
  text ".PRJ_Customer" at 11393.5,-163.5 h70
  text "D" at -416.5,-231.5 h70
  text "D" at 14383.5,-231.5 h70
  text "FILE NAME:" at 11343.5,-323.5 h45
  text ".PCB_File_Name_No_Path" at 11393.5,-443.5 h70
  text "Texas Instruments (TI) and/or its licensors do not warrant the accuracy or completeness of this specification" at 6374,-605.34 h45
  text "ENGINEER:" at 11343.5,-613.5 h45
  text "LAYOUT BY:" at 12848.5,-613.5 h45
  text "or any information contained therein. TI and/or its licensors do not warrant that this design will meet" at 6329.01,-718 h45
  text ".PRJ_Engineer" at 11393.5,-768.49 h70
  text ".PCB_Layout" at 12899,-768.49 h70
  text "the specifications, will be suitable for your application or fit for any particular purpose, or will operate in" at 6329.01,-830.67 h45
  text ".Layer_Name" at 577,-858.49 h60
  text "ALTIUM DESIGNER VERSION:" at 12848.5,-923.5 h45
  text "an implementation. TI and/or its licensors do not warrant that the design is production worthy. You should" at 6329.01,-943.33 h45
  text "completely validate and test your design implementation to confirm the system functionality for your application." at 6374,-1056 h45
  text ".print_Scale" at 11393.5,-1056.83 h70
  text ".Application_BuildNumber" at 12899,-1056.83 h70
  text "1" at 739.84,-1263.5 h70
  text "2" at 3235.5,-1263.5 h70
  text "3" at 5724.84,-1263.5 h70
  text "4" at 8231.51,-1263.5 h70
  text "5" at 10730.5,-1263.5 h70
  text "6" at 13235.5,-1263.5 h70
M10 Fab Notes:
  drawing of 173 lines, arcs and shapes, not listed
  text "DESIGN INFORMATION" at 12378.02,6201 h60
  text "MIN. TRACK WIDTH:" at 11733.46,6021 h60
  text "8" at 12829.7,6021 h60
  text "MIL" at 12984.46,6021 h60
  text "MIN. CLEARANCE:" at 11733.46,5889 h60
  text "0.2" at 12769.7,5889 h60
  text "mm" at 12984.46,5889 h60
  text "MIN. VIA PAD SIZE:" at 11733.46,5757 h60
  text "24" at 12799.71,5757 h60
  text "MIL" at 12984.46,5757 h60
  text "0.05mm (2MIL)" at 12428.46,5615.29 h60
  text "MINIMUM ANNULAR RING" at 11404.23,5611 h60
  text "EXTERNAL" at 13136.46,5611 h60
  text "PER" at 11604.23,5493 h60
  text "IPC-D-275 CLASS 2 LEVEL C" at 11824.23,5493 h60
  text "MIL, HOLES" at 13312.46,5380.71 h60
  text "+/-" at 12920,5380 h60
  text "+/-" at 13774,5380 h60
  text "REGISTRATION TOLERANCES:" at 11404.23,5375 h60
  text "METAL" at 12604,5375 h60
  text "5" at 13180.2,5375 h60
  text "3" at 14013.2,5375 h60
  text "MIL" at 14129.46,5375 h60
  text "+/-" at 13774,5262 h60
  text "HOLE SIZE TOLERANCE (UNLESS OTHERWISE SPECIFIED):" at 11404.23,5257 h60
  text "3" at 14013.2,5257 h60
  text "MIL" at 14129.46,5257 h60
  text "MATERIAL:" at 11329.46,5047.54 h60
  text "FR-4 High Tg" at 12315.9,4907.21 h60
  text "FR-408" at 11750.46,4898.64 h60
  text "OTHER" at 13238.46,4898.64 h60
  text "X" at 12161,4895 h60
  text "62 MIL (1.6mm) +/-10%" at 12070.56,4735.92 h60
  text "THICKNESS:" at 11404.23,4731.64 h60
  text "X" at 11942.4,4731.64 h60
  text "OTHER" at 13355.46,4731.64 h60
  text "TOLERANCE:" at 11404.23,4573.64 h60
  text "X" at 12243.53,4573.64 h60
  text "ANSI IPC-6012 TYPE 3 CLASS 2" at 12430.48,4573.64 h60
  text "OTHER +/-" at 12430.46,4417.64 h60
  text "BOW & TWIST:" at 11404.23,4260.64 h60
  text "X" at 12243.53,4260.64 h60
  text "ANSI IPC-6012 TYPE 3 CLASS 2" at 12430.48,4260.64 h60
  text "OTHER +/-" at 12430.46,4102.13 h60
  text "DRILLING:" at 11329.46,3963.64 h60
  text "REFERENCE:" at 11404.23,3846.64 h60
  text "X" at 12052.46,3846.64 h60
  text "AS SHOWN" at 12239.46,3846.64 h60
  text "X" at 12953.46,3846.64 h60
  text "NC_DRILL FILES" at 13090.46,3846.64 h60
  text "PTH COPPER THICKNESS:" at 11404.23,3688.64 h60
  text "X" at 12534.46,3688.64 h60
  text "20-30 um" at 12671.46,3688.64 h60
  text "OTHER" at 13388.46,3688.64 h60
  text "BOARD FINISH:" at 11329.46,3529.64 h60
  text "SILKSCREEN:" at 11484.68,3411.64 h60
  text "X" at 12433.46,3411.64 h60
  text "TOP" at 12559.46,3411.64 h60
  text "X" at 12943.46,3411.64 h60
  text "BOTTOM" at 13070.46,3411.64 h60
  text "SILKSCREEN COLOR:" at 11484.68,3244.64 h60
  text "X" at 12432.42,3244.64 h60
  text "WHITE" at 12559.46,3244.64 h60
  text "OTHER" at 13070.46,3244.64 h60
  text "X" at 12563.42,3085.44 h60
  text "GREEN" at 12690.46,3085.44 h60
  text "OTHER" at 13308.46,3085.44 h60
  text "SOLDER RESIST COLOR:" at 11484.68,3074.64 h60
  text "X" at 12563.42,2915.44 h60
  text "MATTE" at 12690.46,2915.44 h60
  text "SEMI-GLOSS" at 13308,2914.8 h60
  text "IMMERSION GOLD (ENIG)" at 12390.46,2726.92 h60
  text "ENEPIG" at 13728,2723.64 h60
  text "SURFACE FINISH:" at 11329.46,2722.64 h60
  text "X" at 12203.51,2722.64 h60
  text "IMM. TIN/SILVER OR EQUIV" at 11659,2565.64 h60
  text "OTHER" at 13090.46,2565.64 h60
  text "ARRAY/PANEL:" at 11329.46,2386.64 h60
  text "CUT AND TRIM PER M1 BOARD OUTLINE" at 12390.46,2382.35 h60
  text "N.C. ROUTE" at 12390.46,2230.64 h60
  text "X" at 13069.46,2230.64 h60
  text "V. SCORE" at 13256.46,2230.64 h60
  text "CERTIFICATION:" at 11329.46,2093.64 h60
  text "MATERIALS AND WORKMANSHIP FOR ALL PCBS" at 12054.46,2093.64 h60
  text "TO MEET OR EXCEED THE REQUIREMENTS OF:" at 12054.46,1995.64 h60
  text "X" at 11680.96,1859.13 h60
  text "ANSI IPC-A-600F CLASS ->" at 11819.96,1859.13 h60
  text "X" at 13459.02,1859.13 h60
  text "2" at 13577.96,1859.14 h60
  text "1" at 13262.96,1857.64 h60
  text "3" at 13931.96,1857.64 h60
  text "X" at 12495.02,1699.64 h60
  text "RoHS" at 12631.96,1699.64 h60
  text "OTHER" at 13276.36,1699.64 h60
  text "PER ORDER" at 13673.42,1699.64 h60
  text "ALL BOARDS MUST MEET OR EXCEED UL94-V0 REQUIREMENTS." at 11357,1534 h60
  text "PCB MUST BEAR THE UL94V-0 UL REGISTERED MATERIAL ID NUMBER" at 11357,1414 h60
  text "ADDITIONAL REQUIREMENTS:" at 11329.46,1240.64 h60
  text "MICROSECTION:" at 11404.23,1125.64 h60
  text "YES" at 12309.96,1125.64 h60
  text "REQUIRED" at 13171.46,969.49 h60
  text "BARE BOARD ELEC. TEST:" at 11404.23,966.64 h60
  text "NONE" at 12709.96,966.64 h60
  text "X" at 13044.46,966.64 h60
  text "PER ORDER" at 13763.46,966.64 h60
  text ".Layer_Name" at 577,-858.49 h60
M11 Gerber Information:
  lines w10: -292,-930.17 6308,-930.17 ; -292,-726.83 6310,-726.83 ; -292,-523.5 -292,-1133.5 3713,-1133.5 6310,-1133.5 6310,-523.5 -291.5,-523.5 -291.5,-1133.5 1284,-1133.5 ; 2173,-1133.5 2173,-523.5 ; 3440,-726.83 3440,-523.5 ; 4280,-726.83 4280,-523.5 ; 4902,-1140 4902,-937.17
  text "ALL ARTWORK VIEWED FROM TOP SIDE" at -228.5,-655.67 h60
  text "BOARD #:" at 2248,-655.67 h60
  text ".PRJ_Number" at 2793.5,-655.67 h60
  text "REV:" at 3638,-655.67 h60
  text ".PCB_Rev" at 3929.5,-655.67 h60
  text "SVN REV:" at 4476,-655.67 h60
  text ".VersionControl_RevNumber" at 4982,-655.67 h60
  text "LAYER NAME =" at -228.5,-858.49 h60
  text "TID #:" at 2248,-859 h60
  text ".TID" at 2793.5,-859 h60
  text "PLOT NAME =" at -228.5,-1064.34 h60
  text ".plot_File_Name" at 577,-1064.34 h60
  text "GENERATED    :" at 2250,-1064.34 h60
  text ".Print_Date" at 3119.5,-1064.34 h60
  text ".Print_Time" at 3848.5,-1064.34 h60
  text "TEXAS INSTRUMENTS" at 5113,-1064.34 h60
M12 Stackup:
  drawing of 191 lines, arcs and shapes, not listed
  text "Layer" at 9790.34,7830 h60
  text "Name" at 10200.26,7830 h60
  text "Material" at 11130,7830 h60
  text "Thickness" at 11989.77,7830 h60
  text "Constant" at 12639.6,7830 h60
  text "Board Layer Stack" at 13209.46,7830 h60
  text "1" at 9790.34,7710 h60
  text "Top Overlay" at 10200.26,7710 h60
  text "2" at 9790.34,7590 h60
  text "Top Solder" at 10200.26,7590 h60
  text "Solder Resist" at 11130,7590 h60
  text "0.40mil" at 11989.77,7590 h60
  text "3.5" at 12639.6,7590 h60
  text "3" at 9790.34,7470 h60
  text "Top Layer" at 10200.26,7470 h60
  text "Copper" at 11130,7470 h60
  text "1.40mil" at 11989.77,7470 h60
  text "4" at 9790.34,7350 h60
  text "Dielectric1" at 10200.26,7350 h60
  text "FR-4" at 11130,7350 h60
  text "59.20mil" at 11989.77,7350 h60
  text "4.8" at 12639.6,7350 h60
  text "5" at 9790.34,7230 h60
  text "Bottom Layer" at 10200.26,7230 h60
  text "Copper" at 11130,7230 h60
  text "1.40mil" at 11989.77,7230 h60
  text "6" at 9790.34,7110 h60
  text "Bottom Solder" at 10200.26,7110 h60
  text "Solder Resist" at 11130,7110 h60
  text "0.40mil" at 11989.77,7110 h60
  text "3.5" at 12639.6,7110 h60
  text "7" at 9790.34,6990 h60
  text "Bottom Overlay" at 10200.26,6990 h60
  text ".Layer_Name" at 577,-858.49 h60
M13 Component Bodies Top:
  text ".Layer_Name" at 577,-858.49 h60
M14 Component Bodies Bottom:
  text ".Layer_Name" at 577,-858.49 h60
M15 Courtyards Top:
  text ".Layer_Name" at 577,-858.49 h60
M16 Courtyards Bottom:
  text ".Layer_Name" at 577,-858.49 h60
Drill Drawing:
  lines w10: 5336.09,2630.87 5349.9,2630.87 5363.72,2617.06 5377.53,2630.87 5391.34,2630.87 5377.53,2644.68 5391.34,2658.5 5377.53,2658.5 5363.72,2672.31 5349.9,2658.5 5336.09,2658.5 5349.9,2644.68 5336.09,2630.87 ; 5336.09,2796.63 5391.34,2796.63 5363.72,2741.38 5336.09,2796.63 ; 5336.09,2879.51 5349.9,2879.51 5349.9,2865.7 5377.53,2865.7 5377.53,2879.51 5391.34,2879.51 5391.34,2907.14 5377.53,2907.14 5377.53,2920.95 5349.9,2920.95 5349.9,2907.14 5336.09,2907.14 5336.09,2879.51 ; 5336.09,2990.02 5363.72,3003.83 5391.34,2990.02 5377.53,3017.64 5391.34,3045.27 5363.72,3031.46 5336.09,3045.27 5349.9,3017.64 5336.09,2990.02 ; 5336.09,3114.34 5336.09,3128.15 5349.9,3141.96 5336.09,3155.78 5336.09,3169.59 5349.9,3169.59 5363.72,3155.78 5377.53,3169.59 5391.34,3169.59 5391.34,3155.78 5377.53,3141.96 5391.34,3128.15 5391.34,3114.34 5377.53,3114.34 5363.72,3128.15 5349.9,3114.34 5336.09,3114.34 ; 5336.09,3238.66 5391.34,3238.66 5391.34,3293.91 5336.09,3293.91 5336.09,3238.66
  lines w12: 5286,2579.76 8517.49,2579.76 ; 5286,3325.68 8517.49,3325.68 ; 5623.86,2455.44 5623.86,3450 ; 5955.86,2455.44 5955.86,3450 ; 6592.43,2455.44 6592.43,3450 ; 6851.57,2455.44 6851.57,3450 ; 7226.72,2455.44 7226.72,3450 ; 7951.05,2455.44 7951.05,3450 ; 5286,2455.44 8517.49,2455.44 8517.49,3450 5286,3450 5286,2455.44
  text "Symbol" at 5360.59,3362.98 h72
  text "Quantity" at 5661.16,3362.98 h72
  text "Finished Hole Size" at 5993.16,3362.98 h72
  text "Plated" at 6629.72,3362.98 h72
  text "Hole Type" at 6888.86,3362.98 h72
  text "Drill Layer Pair" at 7264.02,3362.98 h72
  text "Hole Tolerance" at 7988.35,3362.98 h72
  text "12" at 5661.16,3238.66 h60
  text "7.87mil (0.200mm)" at 5993.16,3238.66 h60
  text "PTH" at 6629.72,3238.66 h60
  text "Round" at 6888.86,3238.66 h60
  text "Top Layer - Bottom Layer" at 7264.02,3238.66 h60
  text "13" at 5661.16,3114.34 h60
  text "15.00mil (0.381mm)" at 5993.16,3114.34 h60
  text "PTH" at 6629.72,3114.34 h60
  text "Round" at 6888.86,3114.34 h60
  text "Top Layer - Bottom Layer" at 7264.02,3114.34 h60
  text "4" at 5661.16,2990.02 h60
  text "25.59mil (0.650mm)" at 5993.16,2990.02 h60
  text "PTH" at 6629.72,2990.02 h60
  text "Round" at 6888.86,2990.02 h60
  text "Top Layer - Bottom Layer" at 7264.02,2990.02 h60
  text "3" at 5661.16,2865.7 h60
  text "33.46mil (0.850mm)" at 5993.16,2865.7 h60
  text "PTH" at 6629.72,2865.7 h60
  text "Round" at 6888.86,2865.7 h60
  text "Top Layer - Bottom Layer" at 7264.02,2865.7 h60
  text "16" at 5661.16,2741.38 h60
  text "40.00mil (1.016mm)" at 5993.16,2741.38 h60
  text "PTH" at 6629.72,2741.38 h60
  text "Round" at 6888.86,2741.38 h60
  text "Top Layer - Bottom Layer" at 7264.02,2741.38 h60
  text "2" at 5661.16,2617.06 h60
  text "51.18mil (1.300mm)" at 5993.16,2617.06 h60
  text "PTH" at 6629.72,2617.06 h60
  text "Round" at 6888.86,2617.06 h60
  text "Top Layer - Bottom Layer" at 7264.02,2617.06 h60
  text "50 Total" at 5661.16,2492.74 h60
  text ".Layer_Name" at 577,-858.49 h60
M17 Embedded Cavity:
  text ".Layer_Name" at 577,-858.49 h60
M18 Embedded Assembly:
  text ".Layer_Name" at 577,-858.49 h60
M19 Embedded Keepout:
  text ".Layer_Name" at 577,-858.49 h60

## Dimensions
0,-400 to 1000,-400 on M2 Board Dimensions
0,1250 to 2500,0 on M2 Board Dimensions
2500,0 to 0,1250 on M2 Board Dimensions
